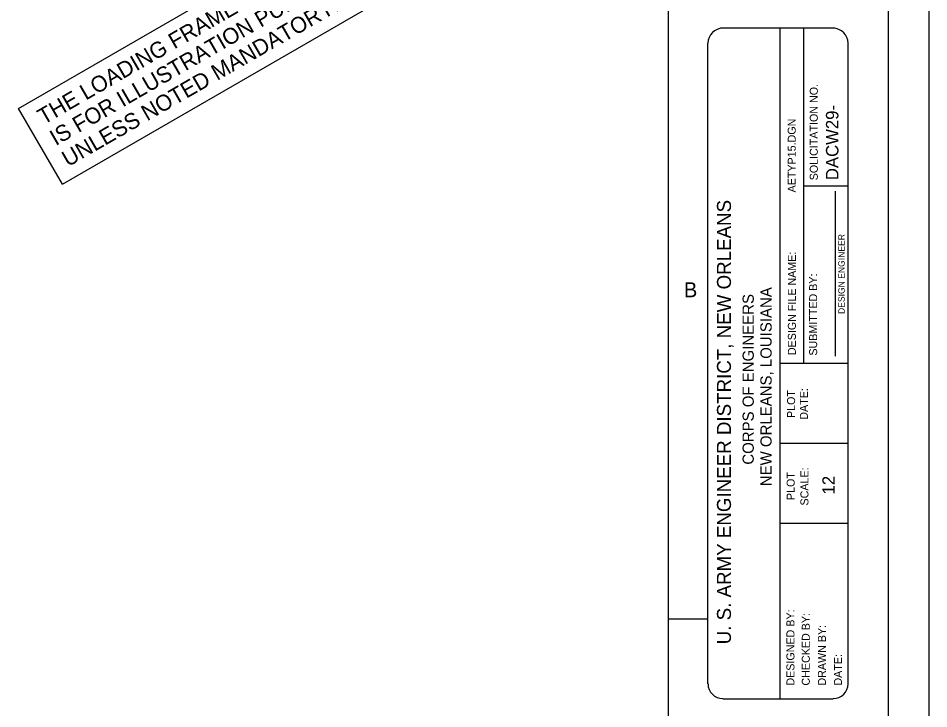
# Model space of a CAD drawing. Extents: x 22378.6 to 22422.6, y 22377.7 to 22411.7.
# Drawn here: x 22411.26 to 22422.65, y 22385.28 to 22393.91 of the extents above; entities that cross this region are included whole.
import ezdxf

# ---------------------------------------------------------------- set-up
doc = ezdxf.new("R2010")
doc.units = 0
for name, color, linetype in [('Level 1', 7, 'Continuous'), ('Level 10', 7, 'Continuous'), ('Level 2', 7, 'Continuous'), ('Level 7', 7, 'Continuous'), ('Level 9', 7, 'Continuous')]:
    doc.layers.add(name, color=color, linetype=linetype)

msp = doc.modelspace()

# ---------------------------------------------------------------- linework, layer by layer
at = {"layer": 'Level 1'}
for p, q in [((22421.469, 22393.779), (22420.041, 22393.779)), ((22420.785, 22393.779), (22420.785, 22385.403))]:
    msp.add_line(p, q, dxfattribs=at)
msp.add_lwpolyline([(22378.629, 22411.659), (22422.645, 22411.659), (22422.645, 22377.651), (22378.629, 22377.651)], close=True, dxfattribs=at)
for points in [[(22421.45, 22393.779), (22420.073, 22393.779)], [(22419.885, 22385.591), (22419.885, 22393.592)], [(22421.637, 22385.591), (22421.637, 22393.592)], [(22420.073, 22385.403), (22421.45, 22385.403)]]:
    msp.add_lwpolyline(points, dxfattribs=at)
for centre, radius, start, end in [((22420.073, 22393.592), 0.188, 90, 180), ((22421.45, 22393.592), 0.187, 0, 90), ((22420.073, 22385.591), 0.187, 180, 270), ((22421.45, 22385.591), 0.187, 270, 0)]:
    msp.add_arc(centre, radius, start, end, dxfattribs=at)
at = {"layer": 'Level 10'}
for p, q in [((22411.269, 22392.778), (22416.767, 22395.953)), ((22411.816, 22391.832), (22417.314, 22395.006)), ((22411.816, 22391.832), (22411.269, 22392.778)), ((22419.393, 22386.399), (22419.885, 22386.399))]:
    msp.add_line(p, q, dxfattribs=at)
at = {"layer": 'Level 2'}
for p, q in [((22421.08, 22393.779), (22421.08, 22389.591)), ((22421.637, 22391.808), (22421.08, 22391.808)), ((22421.481, 22389.682), (22421.481, 22391.743)), ((22421.637, 22389.591), (22420.785, 22389.591)), ((22421.637, 22388.591), (22420.785, 22388.591)), ((22421.637, 22387.591), (22420.785, 22387.591))]:
    msp.add_line(p, q, dxfattribs=at)
at = {"layer": 'Level 9'}
msp.add_line((22422.141, 22378.155), (22422.141, 22411.155), dxfattribs=at)
msp.add_lwpolyline([(22419.393, 22378.155), (22419.393, 22411.155)], dxfattribs=at)

# ---------------------------------------------------------------- texts
at = {"layer": 'Level 1'}
for s, height, p in [('SOLICITATION NO.', 0.10001, (22421.258, 22391.88)), ('AETYP15.DGN', 0.10001, (22420.982, 22391.729)), ('U. S. ARMY ENGINEER DISTRICT, NEW ORLEANS', 0.175, (22420.173, 22386.083)), ('DESIGN ENGINEER', 0.07999, (22421.594, 22390.21)), ('DESIGN FILE NAME:', 0.10001, (22420.984, 22389.696)), ('SUBMITTED BY:', 0.10001, (22421.25, 22389.69)), ('PLOT', 0.1, (22420.974, 22388.91)), ('DATE:', 0.1, (22421.134, 22388.889)), ('SCALE:', 0.1, (22421.141, 22387.817)), ('PLOT', 0.1, (22420.969, 22387.885)), ('DESIGNED BY:', 0.10001, (22420.966, 22385.567)), ('CHECKED BY:', 0.10001, (22421.158, 22385.567)), ('DRAWN BY:', 0.1, (22421.36, 22385.567)), ('DATE:', 0.1, (22421.56, 22385.567))]:
    msp.add_text(s, height=height, rotation=90, dxfattribs=at).set_placement(p)
msp.add_text('B', height=0.187, dxfattribs=at).set_placement((22419.585, 22390.419))
at = {"layer": 'Level 7'}
for s, height, rotation, p in [('THE LOADING FRAME AND TEST APPARATUS', 0.2, 30.0029, (22411.581, 22392.57)), ('IS FOR ILLUSTRATION PURPOSES ONLY,', 0.2, 30.0029, (22411.733, 22392.306)), ('UNLESS NOTED MANDATORY.', 0.2, 30.0029, (22411.885, 22392.043)), ('DACW29-', 0.156, 90, (22421.516, 22391.882)), ('NEW ORLEANS, LOUISIANA', 0.14, 90, (22420.681, 22388.058)), ('CORPS OF ENGINEERS', 0.14, 90, (22420.458, 22388.327)), ('12', 0.156, 90, (22421.471, 22387.955))]:
    msp.add_text(s, height=height, rotation=rotation, dxfattribs=at).set_placement(p)

doc.saveas('drawing.dxf')
